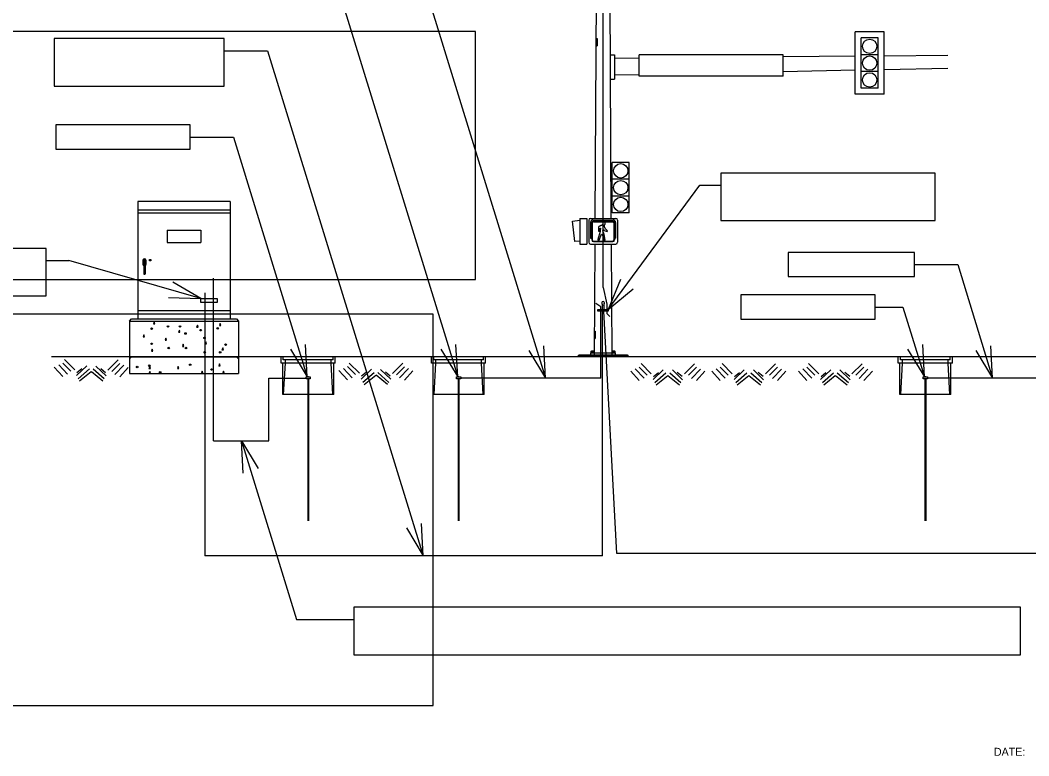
# Model space of a CAD drawing. Extents: x 418532 to 419834, y -565899 to -565296.
# Drawn here: x 418975 to 419505, y -565891 to -565505 of the extents above; entities that cross this region are included whole.
import ezdxf

# ---------------------------------------------------------------- set-up
doc = ezdxf.new("R2010")
doc.units = 0
for name, color, linetype in [('Level 10', 7, 'Continuous'), ('R_Draft', 7, 'Continuous'), ('T_Drafting', 7, 'Continuous'), ('Template', 7, 'Continuous')]:
    doc.layers.add(name, color=color, linetype=linetype)

msp = doc.modelspace()

# ---------------------------------------------------------------- linework, layer by layer
at = {"layer": 'R_Draft'}
for p, q in [((419180.49, -565464.02), (419251, -565693.03)), ((419142.53, -565489.69), (419204.92, -565692.33)), ((419082.42, -565521.13), (419105.15, -565521.13)), ((419105.15, -565521.13), (419186.79, -565786.31)), ((419064.43, -565566.46), (419087.16, -565566.46)), ((419087.16, -565566.46), (419125.92, -565692.33)), ((419283.97, -565657.08), (419332.03, -565591.72)), ((419332.03, -565591.72), (419343.04, -565591.72)), ((419036.99, -565600.25), (419036.99, -565662.01)), ((419085.52, -565600.25), (419036.99, -565600.25)), ((419085.52, -565600.25), (419085.52, -565662.01)), ((419085.52, -565604.94), (419036.99, -565604.94)), ((419085.52, -565606.46), (419036.99, -565606.46)), ((418988.95, -565631.28), (419000.84, -565631.28)), ((419070.09, -565651.28), (419000.84, -565631.28)), ((419039.72, -565631.13), (419039.72, -565633.39)), ((419040.12, -565631.13), (419040.12, -565638.33)), ((419040.91, -565631.13), (419040.91, -565638.33)), ((419041.31, -565631.13), (419041.31, -565633.39)), ((419444.6, -565633.39), (419467.34, -565633.39)), ((419467.34, -565633.39), (419485.7, -565693.03)), ((419040.25, -565638.46), (419040.78, -565638.46)), ((419036.99, -565657.6), (419085.52, -565657.6)), ((419423.97, -565655.74), (419438.61, -565655.74)), ((419438.61, -565655.74), (419449.88, -565692.33)), ((419033.73, -565662.01), (419088.79, -565662.01)), ((419033.73, -565681.87), (419088.79, -565681.87)), ((419091.37, -565726.05), (419120.23, -565819.78)), ((419120.23, -565819.78), (419150.36, -565819.78))]:
    msp.add_line(p, q, dxfattribs=at)
for points in [[(418993.1, -565539.66), (419082.42, -565539.66), (419082.42, -565514.74), (418993.1, -565514.74)], [(418993.95, -565572.84), (419064.43, -565572.84), (419064.43, -565560.07), (418993.95, -565560.07)], [(419343.04, -565610.25), (419455.46, -565610.25), (419455.46, -565585.34), (419343.04, -565585.34)], [(418902.67, -565649.81), (418988.95, -565649.81), (418988.95, -565624.9), (418902.67, -565624.9)], [(419378.37, -565639.77), (419444.6, -565639.77), (419444.6, -565627), (419378.37, -565627)], [(419353.48, -565662.12), (419423.97, -565662.12), (419423.97, -565649.35), (419353.48, -565649.35)]]:
    msp.add_lwpolyline(points, close=True, dxfattribs=at)
for points in [[(419053.09, -565650.66), (419070.09, -565651.28), (419055.38, -565642.74)], [(419290.42, -565641.34), (419283.97, -565657.08), (419297.06, -565646.23)], [(419045.62, -565663.48), (419045.21, -565664.57), (419045.94, -565664.55), (419045.62, -565663.48)], [(419080.22, -565664.3), (419079.82, -565665.4), (419080.55, -565665.37), (419080.22, -565664.3)], [(419058.82, -565667.91), (419058.42, -565669.01), (419059.15, -565668.98), (419058.82, -565667.91)], [(419068.28, -565665.25), (419067.88, -565666.34), (419068.61, -565666.31), (419068.28, -565665.25)], [(419040.18, -565670.32), (419039.78, -565671.42), (419040.5, -565671.39), (419040.18, -565670.32)], [(419051.78, -565672.04), (419051.38, -565673.14), (419052.11, -565673.11), (419051.78, -565672.04)], [(419072.75, -565673.93), (419072.35, -565675.03), (419073.07, -565675), (419072.75, -565673.93)], [(419044.56, -565677.8), (419044.16, -565678.9), (419044.89, -565678.87), (419044.56, -565677.8)], [(419060.89, -565675.3), (419060.49, -565676.4), (419061.21, -565676.37), (419060.89, -565675.3)], [(419081.6, -565677.2), (419081.2, -565678.29), (419081.93, -565678.27), (419081.6, -565677.2)], [(419117.12, -565677.78), (419125.92, -565692.33), (419125, -565675.35)], [(419196.12, -565677.78), (419204.92, -565692.33), (419204, -565675.35)], [(419242.2, -565678.47), (419251, -565693.03), (419250.09, -565676.05)], [(419441.08, -565677.78), (419449.88, -565692.33), (419448.96, -565675.35)], [(419476.9, -565678.47), (419485.7, -565693.03), (419484.79, -565676.05)], [(419079.88, -565685.62), (419079.48, -565686.72), (419080.21, -565686.69), (419079.88, -565685.62)], [(419043.27, -565686.91), (419042.87, -565688.01), (419043.6, -565687.98), (419043.27, -565686.91)], [(419043.27, -565689.58), (419042.87, -565690.68), (419043.6, -565690.65), (419043.27, -565689.58)], [(419058.22, -565686.91), (419057.82, -565688.01), (419058.55, -565687.98), (419058.22, -565686.91)], [(419070.86, -565689.41), (419070.46, -565690.5), (419071.18, -565690.47), (419070.86, -565689.41)], [(419082.03, -565689.41), (419081.63, -565690.5), (419082.36, -565690.47), (419082.03, -565689.41)], [(419092.29, -565743.03), (419091.37, -565726.05), (419100.17, -565740.61)], [(419177.99, -565771.76), (419186.79, -565786.31), (419185.88, -565769.33)]]:
    msp.add_lwpolyline(points, dxfattribs=at)
for centre in [(419044.24, -565667.12), (419052.84, -565665.92), (419059.2, -565665.92), (419062.03, -565669.61), (419070.03, -565667.89), (419078.96, -565666.95), (419044.24, -565675.03), (419072, -565671.93), (419083.09, -565675.46), (419053.23, -565677.27), (419062.27, -565677.27), (419072.09, -565679.5), (419080.25, -565679.5), (419064.48, -565686.06), (419036.68, -565687.24), (419043.02, -565686.55), (419048.76, -565689.99), (419075.77, -565688.52)]:
    msp.add_circle(centre, 0.397, dxfattribs=at)
for centre, radius, start, end in [((419040.51, -565631.13), 0.794, 0, 180), ((419040.51, -565631.13), 0.397, 0, 180), ((419040.51, -565633.39), 0.794, 180, 240), ((419040.51, -565633.39), 0.794, 300, 0), ((419040.25, -565638.33), 0.132, 180, 270), ((419040.78, -565638.33), 0.132, 270, 0)]:
    msp.add_arc(centre, radius, start, end, dxfattribs=at)
at = {"layer": 'T_Drafting'}
for p, q in [((419278.06, -565416.17), (419276.93, -565609.16)), ((419285.55, -565609.16), (419284.42, -565416.17)), ((419281.24, -565645.42), (419281.24, -565442.66)), ((419277.49, -565514.72), (419278.08, -565514.72)), ((419278.08, -565514.72), (419278.06, -565518.51)), ((419413.57, -565544), (419413.57, -565511.23)), ((419428.72, -565511.23), (419413.57, -565511.23)), ((419416.72, -565540.85), (419416.72, -565514.38)), ((419425.57, -565514.38), (419416.72, -565514.38)), ((419425.57, -565540.85), (419425.57, -565514.38)), ((419428.72, -565544), (419428.72, -565511.23)), ((419277.46, -565518.51), (419278.06, -565518.51)), ((419285.04, -565523.22), (419287.29, -565523.22)), ((419287.29, -565523.22), (419287.29, -565536)), ((419300.17, -565525.05), (419287.29, -565525.17)), ((419375.79, -565523.19), (419300.17, -565523.19)), ((419300.17, -565534.53), (419300.17, -565523.19)), ((419375.79, -565534.53), (419375.79, -565523.19)), ((419413.57, -565524.06), (419375.79, -565524.39)), ((419425.57, -565523.2), (419416.72, -565523.2)), ((419462.15, -565523.64), (419428.72, -565523.93)), ((419413.57, -565531.39), (419375.79, -565532.17)), ((419425.57, -565532.03), (419416.72, -565532.03)), ((419462.15, -565530.39), (419428.72, -565531.08)), ((419285.12, -565536), (419287.29, -565536)), ((419300.17, -565533.72), (419287.29, -565533.99)), ((419375.79, -565534.53), (419300.17, -565534.53)), ((419425.57, -565540.85), (419416.72, -565540.85)), ((419428.72, -565544), (419413.57, -565544)), ((419286.07, -565606.24), (419286.07, -565579.77)), ((419294.92, -565579.77), (419286.07, -565579.77)), ((419294.92, -565606.24), (419294.92, -565579.77)), ((419294.92, -565588.59), (419286.07, -565588.59)), ((419294.92, -565597.42), (419286.07, -565597.42)), ((419294.92, -565606.24), (419286.07, -565606.24)), ((419265.21, -565610.68), (419268.99, -565610.07)), ((419266.47, -565621.37), (419265.21, -565610.68)), ((419268.99, -565609.16), (419268.99, -565622.64)), ((419268.99, -565609.16), (419272.77, -565609.16)), ((419272.77, -565609.16), (419272.77, -565622.64)), ((419273.68, -565610.07), (419273.68, -565621.69)), ((419274.58, -565609.16), (419287.89, -565609.16)), ((419274.62, -565611.36), (419274.62, -565619.49)), ((419275.27, -565611.58), (419275.27, -565620.46)), ((419275.57, -565611.58), (419275.57, -565620.46)), ((419275.91, -565610.07), (419286.53, -565610.07)), ((419276.17, -565610.68), (419286.31, -565610.68)), ((419276.17, -565610.98), (419286.31, -565610.98)), ((419286.91, -565611.58), (419286.91, -565620.46)), ((419287.21, -565611.58), (419287.21, -565620.46)), ((419287.82, -565611.36), (419287.82, -565619.49)), ((419288.8, -565610.07), (419288.8, -565621.73)), ((419052.43, -565615.29), (419070.08, -565615.29)), ((419052.43, -565615.29), (419052.43, -565621.9)), ((419070.08, -565615.29), (419070.08, -565621.9)), ((419052.43, -565621.9), (419070.08, -565621.9)), ((419268.99, -565621.06), (419266.47, -565621.37)), ((419274.62, -565619.49), (419275.25, -565619.49)), ((419276.17, -565621.06), (419286.31, -565621.06)), ((419276.17, -565621.37), (419286.31, -565621.37)), ((419287.21, -565619.49), (419287.82, -565619.49)), ((419268.99, -565622.64), (419272.77, -565622.64)), ((419274.62, -565622.64), (419287.89, -565622.64)), ((419276.85, -565622.64), (419276.51, -565680.86)), ((419285.97, -565680.86), (419285.63, -565622.64)), ((419280.54, -565653.82), (419280.86, -565654.68)), ((419280.01, -565693.03), (419280.01, -565657.87)), ((419280.86, -565786.31), (419280.86, -565657.87)), ((419288.41, -565785.2), (419281.53, -565657.87)), ((419032.63, -565663.12), (419033.73, -565662.01)), ((419032.63, -565663.12), (419032.63, -565690.69)), ((419032.63, -565663.12), (419089.89, -565663.12)), ((419088.79, -565662.01), (419089.89, -565663.12)), ((419089.89, -565663.12), (419089.89, -565690.69)), ((419276.59, -565668.41), (419277.08, -565668.41)), ((419277.08, -565668.41), (419277.06, -565672.19)), ((419276.56, -565672.19), (419277.06, -565672.19)), ((419274.77, -565679.76), (419287.71, -565679.76)), ((419274.77, -565680.86), (419274.77, -565679.76)), ((419274.93, -565678.97), (419276.49, -565678.97)), ((419274.93, -565679.76), (419274.93, -565678.97)), ((419275.14, -565678.65), (419276.27, -565678.65)), ((419275.14, -565678.97), (419275.14, -565678.65)), ((419275.45, -565679.76), (419275.45, -565678.97)), ((419275.98, -565679.76), (419275.98, -565678.97)), ((419276.27, -565678.97), (419276.27, -565678.65)), ((419276.49, -565679.76), (419276.49, -565678.97)), ((419285.99, -565678.97), (419287.55, -565678.97)), ((419285.99, -565679.76), (419285.99, -565678.97)), ((419286.14, -565678.97), (419286.14, -565678.65)), ((419286.14, -565678.65), (419287.4, -565678.65)), ((419286.5, -565679.76), (419286.5, -565678.97)), ((419287.03, -565679.76), (419287.03, -565678.97)), ((419287.4, -565678.97), (419287.4, -565678.65)), ((419287.55, -565679.76), (419287.55, -565678.97)), ((419287.71, -565680.86), (419287.71, -565679.76)), ((419176.15, -565681.87), (418991.7, -565681.87)), ((419001.81, -565689.38), (418997.61, -565685.18)), ((419003.91, -565688.68), (418998.55, -565683.31)), ((419021.28, -565688.8), (419026.64, -565683.43)), ((419023.38, -565689.5), (419027.57, -565685.3)), ((419033.73, -565681.87), (419032.63, -565682.97)), ((419089.89, -565682.97), (419088.79, -565681.87)), ((419140.65, -565681.87), (419112.25, -565681.87)), ((419112.25, -565685.17), (419112.25, -565681.87)), ((419140.65, -565685.17), (419112.25, -565685.17)), ((419113.08, -565701.72), (419113.08, -565685.17)), ((419113.36, -565683.52), (419113.36, -565681.87)), ((419139.55, -565683.52), (419113.36, -565683.52)), ((419113.54, -565701.72), (419114.46, -565685.17)), ((419114.46, -565685.17), (419114.46, -565683.52)), ((419138.45, -565685.17), (419138.45, -565683.52)), ((419139.37, -565701.72), (419138.45, -565685.17)), ((419139.55, -565683.52), (419139.55, -565681.87)), ((419139.83, -565701.72), (419139.83, -565685.17)), ((419140.65, -565685.17), (419140.65, -565681.87)), ((419153.3, -565690.51), (419147.93, -565685.14)), ((419709.07, -565681.87), (419149.59, -565681.87)), ((419170.67, -565690.62), (419176.03, -565685.26)), ((419219.59, -565681.87), (419191.19, -565681.87)), ((419191.19, -565685.17), (419191.19, -565681.87)), ((419219.59, -565685.17), (419191.19, -565685.17)), ((419192.02, -565701.72), (419192.02, -565685.17)), ((419192.3, -565683.52), (419192.3, -565681.87)), ((419218.49, -565683.52), (419192.3, -565683.52)), ((419192.48, -565701.72), (419193.4, -565685.17)), ((419193.4, -565685.17), (419193.4, -565683.52)), ((419217.39, -565685.17), (419217.39, -565683.52)), ((419218.31, -565701.72), (419217.39, -565685.17)), ((419218.49, -565683.52), (419218.49, -565681.87)), ((419218.77, -565701.72), (419218.77, -565685.17)), ((419219.59, -565685.17), (419219.59, -565681.87)), ((419268.64, -565680.86), (419268.01, -565681.49)), ((419268.01, -565681.87), (419268.01, -565681.49)), ((419268.01, -565681.49), (419294.47, -565681.49)), ((419268.64, -565680.86), (419293.84, -565680.86)), ((419293.84, -565680.86), (419294.47, -565681.49)), ((419294.47, -565681.87), (419294.47, -565681.49)), ((419306.51, -565690.73), (419301.15, -565685.36)), ((419323.88, -565690.84), (419329.24, -565685.48)), ((419349.04, -565690.73), (419343.68, -565685.36)), ((419366.41, -565690.84), (419371.77, -565685.48)), ((419394.45, -565690.73), (419389.09, -565685.36)), ((419411.82, -565690.84), (419417.19, -565685.48)), ((419464.55, -565681.87), (419436.15, -565681.87)), ((419436.15, -565685.17), (419436.15, -565681.87)), ((419464.55, -565685.17), (419436.15, -565685.17)), ((419436.98, -565701.72), (419436.98, -565685.17)), ((419437.26, -565683.52), (419437.26, -565681.87)), ((419463.45, -565683.52), (419437.26, -565683.52)), ((419437.44, -565701.72), (419438.36, -565685.17)), ((419438.36, -565685.17), (419438.36, -565683.52)), ((419462.35, -565685.17), (419462.35, -565683.52)), ((419463.27, -565701.72), (419462.35, -565685.17)), ((419463.45, -565683.52), (419463.45, -565681.87)), ((419463.73, -565701.72), (419463.73, -565685.17)), ((419464.55, -565685.17), (419464.55, -565681.87)), ((418997.61, -565692.18), (418993.18, -565687.28)), ((419000.18, -565691.01), (418995.52, -565686.11)), ((419004.84, -565691.71), (419010.2, -565686.58)), ((419005.07, -565690.08), (419007.64, -565687.98)), ((419005.77, -565693.35), (419011.6, -565688.21)), ((419006.47, -565694.51), (419012.54, -565689.61)), ((419018.71, -565694.63), (419012.65, -565689.73)), ((419019.41, -565693.46), (419013.58, -565688.33)), ((419020.35, -565691.83), (419014.98, -565686.7)), ((419020.11, -565690.2), (419017.55, -565688.1)), ((419025.01, -565691.13), (419029.67, -565686.23)), ((419027.57, -565692.3), (419032, -565687.4)), ((419032.63, -565690.69), (419089.89, -565690.69)), ((419147, -565694.01), (419142.57, -565689.11)), ((419149.57, -565692.84), (419144.9, -565687.94)), ((419151.2, -565691.21), (419147, -565687.01)), ((419154.23, -565693.54), (419159.59, -565688.41)), ((419154.46, -565691.91), (419157.03, -565689.81)), ((419155.16, -565695.17), (419160.99, -565690.04)), ((419168.8, -565695.29), (419162.97, -565690.16)), ((419169.73, -565693.66), (419164.37, -565688.52)), ((419169.5, -565692.02), (419166.94, -565689.92)), ((419172.76, -565691.32), (419176.96, -565687.12)), ((419174.4, -565692.96), (419179.06, -565688.06)), ((419176.96, -565694.12), (419181.39, -565689.22)), ((419300.22, -565694.23), (419295.79, -565689.33)), ((419302.78, -565693.06), (419298.12, -565688.16)), ((419304.41, -565691.43), (419300.22, -565687.23)), ((419307.44, -565693.76), (419312.81, -565688.63)), ((419307.68, -565692.13), (419310.24, -565690.03)), ((419308.38, -565695.39), (419314.21, -565690.26)), ((419322.02, -565695.51), (419316.19, -565690.38)), ((419322.95, -565693.88), (419317.59, -565688.74)), ((419322.72, -565692.24), (419320.15, -565690.14)), ((419325.98, -565691.54), (419330.18, -565687.34)), ((419327.61, -565693.18), (419332.27, -565688.28)), ((419330.18, -565694.34), (419334.61, -565689.44)), ((419342.74, -565694.23), (419338.31, -565689.33)), ((419345.31, -565693.06), (419340.65, -565688.16)), ((419346.94, -565691.43), (419342.74, -565687.23)), ((419349.97, -565693.76), (419355.33, -565688.63)), ((419350.21, -565692.13), (419352.77, -565690.03)), ((419350.9, -565695.39), (419356.73, -565690.26)), ((419364.54, -565695.51), (419358.72, -565690.38)), ((419365.48, -565693.88), (419360.11, -565688.74)), ((419365.24, -565692.24), (419362.68, -565690.14)), ((419368.51, -565691.54), (419372.7, -565687.34)), ((419370.14, -565693.18), (419374.8, -565688.28)), ((419372.7, -565694.34), (419377.13, -565689.44)), ((419388.16, -565694.23), (419383.73, -565689.33)), ((419390.72, -565693.06), (419386.06, -565688.16)), ((419392.35, -565691.43), (419388.16, -565687.23)), ((419395.39, -565693.76), (419400.75, -565688.63)), ((419395.62, -565692.13), (419398.18, -565690.03)), ((419396.32, -565695.39), (419402.15, -565690.26)), ((419409.96, -565695.51), (419404.13, -565690.38)), ((419410.89, -565693.88), (419405.53, -565688.74)), ((419410.66, -565692.24), (419408.09, -565690.14)), ((419413.92, -565691.54), (419418.12, -565687.34)), ((419415.55, -565693.18), (419420.22, -565688.28)), ((419418.12, -565694.34), (419422.55, -565689.44)), ((419105.86, -565693.03), (419125.35, -565693.03)), ((419125.35, -565693.43), (419125.35, -565692.33)), ((419125.35, -565692.33), (419127.55, -565692.33)), ((419127.55, -565693.43), (419125.35, -565693.43)), ((419126.65, -565692.33), (419126.26, -565692.33)), ((419126.26, -565693.43), (419126.26, -565767.96)), ((419126.33, -565693.43), (419126.33, -565767.96)), ((419126.4, -565693.43), (419126.4, -565767.96)), ((419126.45, -565693.43), (419126.45, -565767.96)), ((419126.52, -565693.43), (419126.52, -565767.96)), ((419126.58, -565693.43), (419126.58, -565767.96)), ((419126.65, -565693.43), (419126.65, -565767.96)), ((419127.55, -565692.33), (419127.55, -565693.43)), ((419155.86, -565696.34), (419161.92, -565691.44)), ((419168.1, -565696.46), (419162.04, -565691.56)), ((419204.29, -565693.43), (419204.29, -565692.33)), ((419204.29, -565692.33), (419206.49, -565692.33)), ((419206.49, -565693.43), (419204.29, -565693.43)), ((419205.59, -565692.33), (419205.2, -565692.33)), ((419205.2, -565693.43), (419205.2, -565767.96)), ((419205.27, -565693.43), (419205.27, -565767.96)), ((419205.34, -565693.43), (419205.34, -565767.96)), ((419205.39, -565693.43), (419205.39, -565767.96)), ((419205.46, -565693.43), (419205.46, -565767.96)), ((419205.52, -565693.43), (419205.52, -565767.96)), ((419205.59, -565693.43), (419205.59, -565767.96)), ((419206.49, -565692.33), (419206.49, -565693.43)), ((419280.01, -565693.03), (419206.49, -565693.03)), ((419309.08, -565696.56), (419315.14, -565691.66)), ((419321.32, -565696.68), (419315.25, -565691.78)), ((419351.6, -565696.56), (419357.67, -565691.66)), ((419363.84, -565696.68), (419357.78, -565691.78)), ((419397.02, -565696.56), (419403.08, -565691.66)), ((419409.26, -565696.68), (419403.2, -565691.78)), ((419449.25, -565693.43), (419449.25, -565692.33)), ((419449.25, -565692.33), (419451.45, -565692.33)), ((419451.45, -565693.43), (419449.25, -565693.43)), ((419450.55, -565692.33), (419450.16, -565692.33)), ((419450.16, -565693.43), (419450.16, -565767.96)), ((419450.23, -565693.43), (419450.23, -565767.96)), ((419450.3, -565693.43), (419450.3, -565767.96)), ((419450.35, -565693.43), (419450.35, -565767.96)), ((419450.42, -565693.43), (419450.42, -565767.96)), ((419450.48, -565693.43), (419450.48, -565767.96)), ((419450.55, -565693.43), (419450.55, -565767.96)), ((419451.45, -565692.33), (419451.45, -565693.43)), ((419526.94, -565693.03), (419451.45, -565693.03)), ((419139.83, -565701.72), (419113.08, -565701.72)), ((419218.77, -565701.72), (419192.02, -565701.72)), ((419463.73, -565701.72), (419436.98, -565701.72)), ((419076.69, -565726.05), (419105.86, -565726.05)), ((419280.86, -565786.31), (419072.12, -565786.31)), ((419527.79, -565785.2), (419288.41, -565785.2))]:
    msp.add_line(p, q, dxfattribs=at)
for points in [[(419278.85, -565613.59), (419278.73, -565615.91), (419279.44, -565615.91), (419279.63, -565614.38), (419279.79, -565614.38), (419279.61, -565615.74), (419279.61, -565615.98), (419278.39, -565620.28), (419278.39, -565620.44), (419278.88, -565620.82), (419279.09, -565620.65), (419280.39, -565617.4), (419280.92, -565618.01), (419281.54, -565620.88), (419282.35, -565620.61), (419281.78, -565617.57), (419281.01, -565615.76), (419281.52, -565614.84), (419281.87, -565615.51), (419283.31, -565616.07), (419283.59, -565615.68), (419282.23, -565614.53), (419281.87, -565613.08), (419281.93, -565612.87), (419281.93, -565612.64), (419282, -565612.6)], [(419076.69, -565726.05), (419076.69, -565640.55)], [(419072.12, -565648.31), (419072.12, -565786.31)], [(419281.24, -565645.42), (419283.19, -565654.27), (419283.19, -565654.27), (419283.19, -565659.1), (419283.19, -565659.1), (419284.82, -565660.66)], [(419280.01, -565657.08), (419280.01, -565655.63), (419277.4, -565653.89)], [(419281.83, -565653.82), (419281.53, -565654.61), (419281.53, -565654.61), (419281.53, -565657.08)], [(419280.86, -565657.08), (419280.86, -565654.63), (419280.86, -565654.91), (419280.83, -565654.95), (419280.84, -565654.94)], [(419105.86, -565726.05), (419105.86, -565693.03)]]:
    msp.add_lwpolyline(points, dxfattribs=at)
for points in [[(419070.09, -565651.28), (419078.72, -565651.28), (419078.72, -565653.26), (419070.09, -565653.26)], [(419278.51, -565657.08), (419283.97, -565657.08), (419283.97, -565657.87), (419278.51, -565657.87)], [(419150.36, -565838.32), (419500.36, -565838.32), (419500.36, -565813.4), (419150.36, -565813.4)]]:
    msp.add_lwpolyline(points, close=True, dxfattribs=at)
for centre, radius in [((419421.15, -565518.8), 3.78), ((419421.15, -565527.63), 3.78), ((419421.15, -565536.45), 3.78), ((419290.5, -565584.2), 3.78), ((419290.5, -565593.02), 3.78), ((419290.5, -565601.84), 3.78), ((419043.5, -565631.13), 0.414)]:
    msp.add_circle(centre, radius, dxfattribs=at)
for centre, radius, start, end in [((419274.58, -565610.07), 0.907, 90, 180), ((419275.91, -565611.36), 1.29, 90, 180), ((419276.17, -565611.58), 0.907, 90, 180), ((419276.17, -565611.58), 0.605, 90, 180), ((419286.31, -565611.58), 0.907, 0, 90), ((419286.31, -565611.58), 0.605, 0, 90), ((419286.53, -565611.36), 1.29, 0, 90), ((419287.89, -565610.07), 0.907, 0, 90), ((419274.62, -565621.69), 0.945, 180, 270), ((419276.17, -565620.46), 0.907, 180, 270), ((419276.17, -565620.46), 0.605, 180, 270), ((419286.31, -565620.46), 0.605, 270, 0), ((419286.31, -565620.46), 0.907, 270, 0), ((419287.89, -565621.73), 0.907, 270, 0), ((419281.2, -565653.52), 0.721, 336.8014, 203.8059), ((419281.2, -565653.52), 0.721, 239.5345, 239.7436)]:
    msp.add_arc(centre, radius, start, end, dxfattribs=at)
msp.add_ellipse((419281.7, -565611.91), major_axis=(0, -0.761), ratio=0.9, start_param=0.463156, end_param=5.216339, dxfattribs=at)
msp.add_spline([(419281.1, -565612.28), (419281.02, -565612.41), (419280.91, -565612.47), (419280.78, -565612.58), (419280.63, -565612.7), (419280.08, -565612.98), (419279.82, -565613.1), (419279.56, -565613.21), (419279.21, -565613.4), (419279.05, -565613.46), (419278.85, -565613.59)], degree=3, dxfattribs=at)
at = {"layer": 'Template'}
for points in [[(419214.2, -565511.02), (418906.32, -565511.02), (418906.32, -565641.34), (419214.2, -565641.34)], [(419191.97, -565659.48), (418928.54, -565659.48), (418928.54, -565865.04), (419191.97, -565865.04)]]:
    msp.add_lwpolyline(points, close=True, dxfattribs=at)

# ---------------------------------------------------------------- texts
at = {"layer": 'Level 10'}
msp.add_text('DATE:  ', height=4.2, rotation=360, dxfattribs=at).set_placement((419486.33, -565891.43))

doc.saveas('drawing.dxf')
